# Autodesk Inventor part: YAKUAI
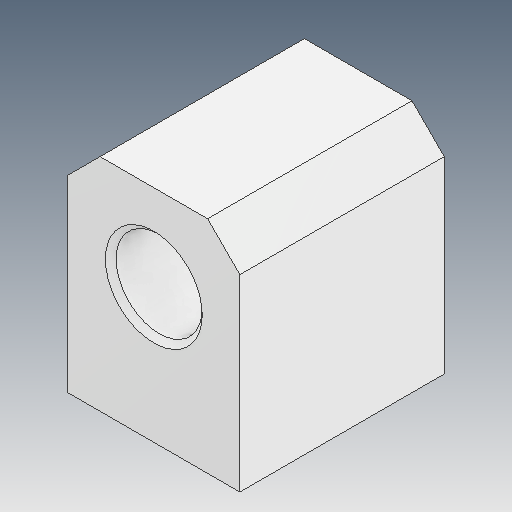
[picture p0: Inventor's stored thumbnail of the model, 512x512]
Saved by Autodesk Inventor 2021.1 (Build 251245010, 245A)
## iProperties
Created: 2021-05
Part Number: YAKUAI
Material: Ogólny
Document SubType Name: Modeling
Designer: user
Density: 1 g/cm^3
Appearance: Domyślna
Author: user
Revision Number: ÈÎºÎ
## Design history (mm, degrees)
feature "ÊäÈë1"
node "Bryła1"
